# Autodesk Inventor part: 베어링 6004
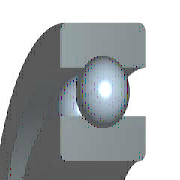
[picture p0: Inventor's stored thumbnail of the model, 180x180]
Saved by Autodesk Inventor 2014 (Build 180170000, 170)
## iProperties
Created: 2012-02
Part Number: 베어링 6004
Material: 강철, 연강
Description: 깊은 그루브 볼 베어링
Document SubType Name: Modeling
Standard: KS B 2023
Designer: mduedu
Standards Organization: KS
Language: ko-KR
Size Designation: 6004 - 20 x 42 x 12
Categories: <MemberInstance><Categories><Category DisplayName="샤프트 부품" InternalName="7f7aeb1f-a693-4053-b835-cee3144e0d98" Mnemonic="SHFT"><Category DisplayName="베어링" Inter
Density: 1 g/cm^3
Appearance: 노란색
IsCustomPart: 1
Author: mduedu
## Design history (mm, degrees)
sketch "스케치" dims "d0" = 5.72 (= -0.26 x WD + 0.26 x BD)
  geometry: L1 (3.14, 15.5)-(8.86, 15.5); L2 (6, 15.5)-(6, 12.64); L3 (6, 15.5)-(6, 18.36); L4 (3.875, 13.586)-(0, 13.586); L5 (0, 10)-(12, 10); L6 (3.875, 17.414)-(0, 17.414); L7 (0, 21)-(12, 21); L8 (12, 10)-(12, 13.586); L9 (8.125, 13.586)-(12, 13.586); L10 (8.125, 17.414)-(12, 17.414); L11 (12, 21)-(12, 17.414); L12 (-1.4, 0)-(8.4, 0) reference; L13 (0, -0.3)-(0, 5.3) reference
  constraints: 22 end point, 4 point on line, 2 collinear, 2 perpendicular, 2 symmetric about line, 1 midpoint, 1 parallel, 14 other
  dimensions: "d9" = 20 diameter of L5 L12 (= WD); "d11" = 42 diameter of L7 L12 (= BD); "d12" = 12 distance between parallel lines of L8 L13 (= KB); "d13" = 27.172 diameter of L9 L12 (= 0.326 x BD + 0.674 x WD)
revolve "본체" stored, may be unused: angle "d6" = 90 deg
revolve "볼" stored, may be unused: angle "d7" = 90 deg
pattern_circular "IDS_ARRAYBALL[SIMPL:T]" dims angle "d3" = 360 deg
body "Solid1"
fillet "모깎기1" dims "d1" = 0.6 (= KRS)
other parameters: "WD" = 20 [user parameter; used in 5 equation terms], "BD" = 42 [user parameter; used in 5 equation terms], "KB" = 12 [user parameter; used in 1 equation term], "KRS" = 0.6 [user parameter; used in 1 equation term], "d4" = 0, "d5" = 0, "d8" = 0, "d14" = 0, "d15" = 0, "BBA" = 0 [user parameter], "BC0" = 5000000 [user parameter], "BC" = 9360000 [user parameter], "BR" = 21 (= 0.5 x BD) [user parameter]
